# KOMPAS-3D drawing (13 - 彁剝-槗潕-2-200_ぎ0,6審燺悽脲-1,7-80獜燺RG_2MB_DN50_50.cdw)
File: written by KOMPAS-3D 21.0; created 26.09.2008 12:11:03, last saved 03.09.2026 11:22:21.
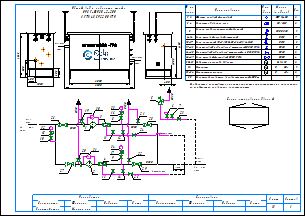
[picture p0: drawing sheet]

Sheets 1-2: A3, landscape

Document properties: Наименование: Макро:21; Автор: RaskoAdmin; Форматы листов документа: 2xA3; Полное имя файла: \\UR38nt01\Departments\КТО\КБ ПУРДГ\Заявки\Прайс-лист на типовые шкафы ГРПШ\ПРДГ_стандарт_20_03_2026\ПРДГ с RG_2MB\ПРДГ-ШУЭО-2-200_до0,6МПа_Рвых-1,7-80кПа_RG_2MB_DN50_50.cdw

Title block, sheet 1: Наименование: Пункт учета газа / ПУГ-Ш-400-Р / ЛГТИ.485922.001ТУ; designation: ЛГТИ.03.4411141; sheet number: 1; Количество листов документа: 2; organisation: ООО "ЭЛЬСТЕР Газэлектроника"; Форматы листов документа: A3; stored path: C:\Рабочие документы\Компас\ПУГ\Схема.cdw; Разработал: Устинов; Проверил: Кошкин; Утвердил: Кошкин
Title block, sheet 2: sheet number: 2; stored path: D:\Рабочие документы\Заявки\ПУРДГ\ПУРДГ-ШУЭО-2-100-Р 4411220.cdw; designation, second copy: ЛГТИ.03.4411141-

Views: Вид 1, Вид 2
Referenced files: wcvoit.frw
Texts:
  Normal
  Вход
  газа
  PDI
  Выход
  Р=     кПа
  DN50
  DN20
  Импульс DN20
  ≥5DN
  HYSWLongFangSong
  № на
  схеме
  Усл.
  обозн.
  Марка
  (модель)
  Кол.
  Фильтр газовый фланцевый
  ФГ 16-50
  Регулятор давления газа
  RG/2MB
  Клапан предохранительный сбросной
  КПС DN20
  Кран шаровой газовый латунный
  DN15
  Кран кнопочный VE-РАСКО-НЗ-1,6-G1/2-М20
  Кран шаровой "под приварку" штуцерный DN20 PN16
  Кран шаровой "под приварку" штуцерный п/п DN20 PN16
  Кран шаровой фланцевый DN50 PN16
  Индикатор перепада давления
  Delta 15
  Манометр
  Манометр-напоромер
  Электрообогреватель взрывозащищенный 400Вт
  0...     МПа
  0...     кПа
  Общий вид и габариты шкафа
  ПРДГ-ШУЭО-2-200
  Выход газа
  Вход газа
  Р=       МПа
  logo-rasko-ge.png
  Схема открывания дверей
  Предприятие изготовитель может заменять комплектующие на аналогичные,
  не ухудшающие заявленных характеристик.
  Должность
  Конструктор
  Фамилия
  Подпись
  Дата
  Согласовано
  Максимкин
  Лист
  Листов
  POLYLINE_STYLE_0.18_RGB_0_0_0
  POLYLINE_STYLE_0.50_RGB_0_0_0
  POLYLINE_STYLE_0.34_RGB_0_0_0
  PHANTOM_RGB_0_0_0_SC_1_THICK_0.18
  K5LT_THIN_RGB_0_0_0_THICK_0.18
  K5LT32769_RGB_0_0_0_THICK_0.18
  K5LT12_RGB_0_0_0_SC_1_THICK_0.18
  K5LT_DASHED_RGB_0_0_0_SC_1_THICK_0.18
  ACISOTGL_RGB_0_0_0_SC_0.8_THICK_0.25
  CONTINUOUS_RGB_0_127_31_THICK_0.3
  CONTINUOUS_RGB_0_0_255_THICK_0.35
  CONTINUOUS_RGB_255_0_0_THICK_0.35
  POLYLINE_STYLE_0.25_RGB_0_0_0
  CONTINUOUS_RGB_0_0_0_THICK_0.5
  POLYLINE_STYLE_0.35_RGB_0_0_255
  CONTINUOUS_RGB_0_0_0_THICK_0.4
  CONTINUOUS_RGB_0_0_0_THICK_0.35
  Без оформления
Dimensions and other numbers on the sheet: 1; 2; 3; 4; 5; 10; 27; 28; 29; 23; 8; 12; 19; 20; 21; 22; 25; 24; 30; 31; 15; 16; 26; 6; 7; 11; 14; 13; 33; 1, 2; 3, 4; 6-14; 9; 15-17; 19-23; 24-25; 26-29; 30-31; 32; 33-34; 35; 1000; 400; 1050; 500; 305; 2000; 4130; 1565; 2300; 17; 34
